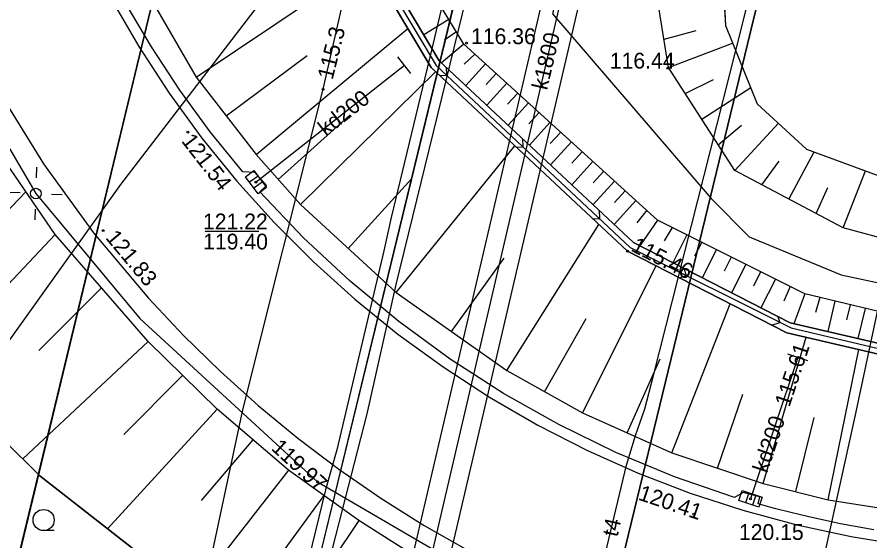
# Model space of a CAD drawing. Extents: x 6424617 to 6425697, y 5665845 to 5667190.
# Drawn here: x 6425461.6 to 6425502.01, y 5666814.14 to 5666838.98 of the extents above; entities that cross this region are included whole.
import ezdxf

# ---------------------------------------------------------------- set-up
doc = ezdxf.new("R2010")
doc.units = 0
for name, color, linetype in [('Warstwa 1', 7, 'Continuous'), ('Warstwa 12', 7, 'Continuous'), ('Warstwa 13', 7, 'Continuous'), ('Warstwa 14', 7, 'Continuous'), ('Warstwa 15', 7, 'Continuous'), ('Warstwa 2', 7, 'Continuous'), ('Warstwa 20', 7, 'Continuous'), ('Warstwa 21', 7, 'Continuous'), ('Warstwa 25', 7, 'Continuous'), ('Warstwa 4', 7, 'Continuous'), ('Warstwa 6', 7, 'Continuous'), ('Warstwa 61', 7, 'Continuous'), ('Warstwa 8', 7, 'Continuous'), ('Warstwa 9', 7, 'Continuous')]:
    doc.layers.add(name, color=color, linetype=linetype)

msp = doc.modelspace()

# ---------------------------------------------------------------- linework, layer by layer
at = {"layer": 'Warstwa 1'}
for p, q in [((6425474.6, 5666748.65), (6425522.252, 5666945.035)), ((6425474.6, 5666748.65), (6425522.252, 5666945.035)), ((6425454.155, 5666782.149), (6425471.236, 5666853.116)), ((6425454.155, 5666782.149), (6425471.236, 5666853.116))]:
    msp.add_line(p, q, dxfattribs=at)
at = {"layer": 'Warstwa 12'}
for points in [[(6425454.75, 5666812.915), (6425455.753, 5666816.883), (6425457.009, 5666817.738), (6425466.513, 5666831.046), (6425477.951, 5666845.959), (6425477.163, 5666847.339), (6425475.812, 5666851.526), (6425475.173, 5666855.074), (6425474.407, 5666861.19), (6425474.538, 5666868.989), (6425475.24, 5666876.27), (6425477.752, 5666888.602), (6425479.441, 5666893.041), (6425480.828, 5666893.587), (6425484.849, 5666908.144), (6425470.76, 5666912.634), (6425469.827, 5666913.063), (6425472.078, 5666923.598), (6425472.03, 5666923.61), (6425482.03, 5666965.191), (6425489.31, 5666994.281), (6425496.49, 5667021.647)], [(6425470.675, 5666812.723), (6425472.304, 5666820.347), (6425476.107, 5666835.553), (6425479.576, 5666850.831), (6425493.276, 5666901.432), (6425493.535, 5666902.072), (6425493.16, 5666902.53), (6425486.027, 5666904.729), (6425481.07, 5666906.403), (6425469.466, 5666909.139), (6425469.101, 5666909.586), (6425469.483, 5666910.214), (6425471.98, 5666923.618), (6425472.03, 5666923.61), (6425482.03, 5666965.191), (6425489.31, 5666994.281), (6425496.49, 5667021.647)], [(6425499.608, 5666812.372), (6425501.312, 5666820.03), (6425502.717, 5666826.643), (6425504.653, 5666835.914), (6425506.015, 5666841.883), (6425506.579, 5666844.134), (6425507.337, 5666847.688), (6425511.705, 5666865.996), (6425515.14, 5666880.945), (6425517.137, 5666889.164), (6425519.622, 5666899.265), (6425524.222, 5666918.678), (6425526.588, 5666928.262), (6425527.475, 5666931.839)], [(6425489.22, 5666812.497), (6425490.474, 5666817.727), (6425490.896, 5666819.13), (6425491.336, 5666820.398), (6425491.737, 5666821.916), (6425495.964, 5666838.649), (6425497.689, 5666845.721), (6425498.913, 5666850.556), (6425503.322, 5666868.321), (6425505.296, 5666876.359), (6425505.681, 5666877.85), (6425506.028, 5666879.322), (6425508.389, 5666888.668), (6425512.199, 5666904.697), (6425513.188, 5666908.441), (6425515.663, 5666918.716), (6425518.264, 5666929.68), (6425518.543, 5666931.101)], [(6425497.683, 5666902.344), (6425491.319, 5666877.188), (6425485.367, 5666852.273), (6425479.594, 5666828.428), (6425475.759, 5666812.66)], [(6425480.155, 5666812.607), (6425490.44, 5666856.731)], [(6425492.103, 5666856.276), (6425481.921, 5666812.585)], [(6425454.04, 5666850.53), (6425455.4, 5666845.1), (6425457.01, 5666840.69), (6425459.99, 5666834.85), (6425462.49, 5666830.61), (6425467.42, 5666824.69), (6425475.84, 5666816.94), (6425483.301, 5666812.571)], [(6425472.92, 5666831.15), (6425479.95, 5666836.7)], [(6425498.59, 5666822.84), (6425496.35, 5666816.13)]]:
    msp.add_lwpolyline(points, dxfattribs=at)
at = {"layer": 'Warstwa 14'}
msp.add_line((6425473.055, 5666828.808), (6425470.509, 5666828.808), dxfattribs=at)
for centre in [(6425476.107, 5666835.553), (6425472.92, 5666831.15), (6425498.59, 5666822.84), (6425475.84, 5666816.94), (6425496.35, 5666816.13)]:
    msp.add_circle(centre, 0.045, dxfattribs=at)
at = {"layer": 'Warstwa 2'}
msp.add_lwpolyline([(6425506.88, 5666899.5), (6425503.781, 5666900.196), (6425486.964, 5666839.13), (6425494.478, 5666830.381), (6425496.276, 5666828.558), (6425500.644, 5666826.749), (6425510.918, 5666824.552), (6425520.412, 5666825.171), (6425529.858, 5666828.662), (6425537.889, 5666834.639), (6425544.658, 5666842.259), (6425549.605, 5666852.483), (6425550.773, 5666856.833), (6425551.852, 5666866.697), (6425550.934, 5666876.787), (6425548.326, 5666886.387), (6425542.173, 5666894.101), (6425528.149, 5666899.626), (6425515.187, 5666901.43), (6425512.303, 5666898.502), (6425510.878, 5666898.777)], dxfattribs=at)
msp.add_circle((6425462.49, 5666830.61), 0.25, dxfattribs=at)
at = {"layer": 'Warstwa 20'}
for points in [[(6425553.362, 5666853.356), (6425550.94, 5666852.09), (6425549.89, 5666849.42), (6425546.52, 5666842.87), (6425542.73, 5666837.38), (6425535.81, 5666831.03), (6425527.38, 5666826.39), (6425518.91, 5666823.71), (6425508.93, 5666823.45), (6425498.92, 5666825.85), (6425491.94, 5666829.35), (6425482.77, 5666837.69), (6425477.07, 5666847.09), (6425474.62, 5666856.16), (6425473.75, 5666866.03), (6425474.86, 5666875.89), (6425476.95, 5666886.84), (6425486.39, 5666917.66), (6425485.183, 5666918.688), (6425484.95, 5666918.78)], [(6425527.173, 5666830.091), (6425521.012, 5666827.921), (6425513.022, 5666826.965), (6425506.638, 5666827.381), (6425500.735, 5666828.978), (6425495.602, 5666831.701), (6425492.469, 5666836.579), (6425491.597, 5666841.997), (6425492.669, 5666848.17), (6425494.303, 5666855.052), (6425496.377, 5666864.638), (6425499.03, 5666874.163), (6425501.822, 5666883.666), (6425504.791, 5666895.166), (6425507.053, 5666899.127)], [(6425461.776, 5666863.542), (6425462.587, 5666855.825), (6425463.836, 5666850.201), (6425464.965, 5666846.225), (6425466.204, 5666842.856), (6425470.084, 5666836.133), (6425472.923, 5666832.458), (6425475.027, 5666830.092), (6425479.556, 5666825.924), (6425484.798, 5666822.213), (6425488.384, 5666820.211), (6425492.62, 5666818.321), (6425496.943, 5666816.862), (6425500.032, 5666816.086), (6425505.767, 5666815.182), (6425511.615, 5666814.977), (6425517.376, 5666815.473), (6425523.099, 5666816.62), (6425528.634, 5666818.471)], [(6425481.867, 5666812.588), (6425481.221, 5666812.926), (6425477.791, 5666815.103), (6425474.465, 5666817.491), (6425471.081, 5666820.378), (6425467.805, 5666823.596), (6425463.4, 5666828.674), (6425460.629, 5666832.713), (6425458.029, 5666837.277), (6425455.963, 5666841.717), (6425454.719, 5666845.111), (6425453.384, 5666849.709)]]:
    msp.add_lwpolyline(points, dxfattribs=at)
at = {"layer": 'Warstwa 21'}
for p, q in [((6425480.26, 5666836.308), (6425479.64, 5666837.092)), ((6425499.065, 5666822.683), (6425498.115, 5666822.997))]:
    msp.add_line(p, q, dxfattribs=at)
for points in [[(6425484.95, 5666918.78), (6425484.833, 5666917.264), (6425485.3, 5666917.095), (6425478.237, 5666897.116), (6425475.766, 5666887.097), (6425473.486, 5666876.065), (6425472.598, 5666865.688), (6425473.371, 5666855.87), (6425475.777, 5666846.714), (6425481.602, 5666836.906), (6425490.809, 5666828.287), (6425498.233, 5666824.471), (6425508.632, 5666822.063), (6425519.743, 5666822.432), (6425527.817, 5666824.757), (6425536.828, 5666829.656), (6425543.832, 5666835.802), (6425548.243, 5666841.884), (6425551.55, 5666848.658), (6425553.362, 5666853.356)], [(6425528.009, 5666824.294), (6425519.824, 5666821.941), (6425508.583, 5666821.554), (6425498.064, 5666824.004), (6425490.521, 5666827.872), (6425481.216, 5666836.593), (6425475.303, 5666846.513), (6425472.88, 5666855.789), (6425472.098, 5666865.687), (6425472.997, 5666876.134), (6425475.278, 5666887.206), (6425477.76, 5666897.255), (6425484.833, 5666917.264)], [(6425507.053, 5666899.127), (6425505.53, 5666891.812), (6425504.069, 5666884.586), (6425503.174, 5666880.42), (6425501.832, 5666873.682), (6425500.85, 5666868.589), (6425500.275, 5666865.548), (6425499.288, 5666861.334), (6425498.064, 5666856.115), (6425496.122, 5666847.767), (6425494.952, 5666842.767), (6425495.156, 5666838.572), (6425496.67, 5666834.863), (6425499.002, 5666832.72), (6425505.401, 5666830.354), (6425509.993, 5666829.821), (6425515.794, 5666829.796), (6425520.41, 5666830.593), (6425526.02, 5666832.712)], [(6425468.392, 5666812.751), (6425462.681, 5666817.231), (6425457.481, 5666822.356), (6425456.019, 5666822.263), (6425453.384, 5666849.709)]]:
    msp.add_lwpolyline(points, dxfattribs=at)
at = {"layer": 'Warstwa 25'}
for centre in [(6425482.891, 5666837.735), (6425492.435, 5666836.548), (6425469.695, 5666833.516), (6425465.676, 5666828.85), (6425490.521, 5666827.872), (6425493.663, 5666815.401)]:
    msp.add_circle(centre, 0.045, dxfattribs=at)
at = {"layer": 'Warstwa 4'}
for p, q in [((6425473.017, 5666831.439), (6425472.615, 5666831.142)), ((6425473.225, 5666831.158), (6425472.823, 5666830.861)), ((6425496.266, 5666816.423), (6425496.103, 5666815.95)), ((6425496.597, 5666816.31), (6425496.434, 5666815.837))]:
    msp.add_line(p, q, dxfattribs=at)
for points in [[(6425462.52, 5666831.359), (6425462.539, 5666831.859)], [(6425461.741, 5666830.64), (6425461.241, 5666830.659)], [(6425463.239, 5666830.58), (6425463.739, 5666830.561)], [(6425462.46, 5666829.861), (6425462.441, 5666829.361)]]:
    msp.add_lwpolyline(points, dxfattribs=at)
for points in [[(6425472.824, 5666831.701), (6425473.418, 5666830.897), (6425473.016, 5666830.599), (6425472.422, 5666831.403)], [(6425495.958, 5666816.529), (6425496.904, 5666816.204), (6425496.742, 5666815.731), (6425495.796, 5666816.056)]]:
    msp.add_lwpolyline(points, close=True, dxfattribs=at)
at = {"layer": 'Warstwa 6'}
msp.add_line((6425463.36, 5666814.627), (6425462.86, 5666814.627), dxfattribs=at)
for points in [[(6425493.084, 5667022.41), (6425437.407, 5666792.342), (6425454.155, 5666782.149), (6425471.236, 5666853.116), (6425495.139, 5666950.762), (6425496.12, 5666954.85), (6425485.36, 5666958.9), (6425501.348, 5667020.558)], [(6425474.6, 5666748.65), (6425522.252, 5666945.035), (6425496.12, 5666954.85), (6425495.139, 5666950.762), (6425471.236, 5666853.116), (6425454.155, 5666782.149)], [(6425569.514, 5666914.463), (6425559.46, 5666924.76), (6425550.86, 5666931.17), (6425537.49, 5666938.32), (6425528.13, 5666942.39), (6425522.252, 5666945.035), (6425474.6, 5666748.65), (6425499.79, 5666763.64), (6425538.28, 5666785.28), (6425540.993, 5666787.253)], [(6425502.194, 5666814.659), (6425501.402, 5666814.798), (6425500.613, 5666814.95), (6425499.826, 5666815.115), (6425499.042, 5666815.292), (6425498.26, 5666815.481), (6425497.482, 5666815.682), (6425496.707, 5666815.896), (6425496.783, 5666816.235), (6425496.007, 5666816.439), (6425495.592, 5666816.196), (6425492.75, 5666817.183), (6425489.972, 5666818.337), (6425487.267, 5666819.654), (6425484.646, 5666821.131), (6425482.118, 5666822.762), (6425479.692, 5666824.54), (6425477.376, 5666826.46), (6425475.178, 5666828.515), (6425473.107, 5666830.697), (6425473.422, 5666830.991), (6425472.883, 5666831.601), (6425472.294, 5666831.632), (6425470.756, 5666833.537), (6425469.313, 5666835.515), (6425467.968, 5666837.562), (6425466.726, 5666839.672)]]:
    msp.add_lwpolyline(points, dxfattribs=at)
msp.add_circle((6425462.86, 5666815.127), 0.5, dxfattribs=at)
at = {"layer": 'Warstwa 61'}
for points in [[(6425481.038, 5666812.596), (6425491.4, 5666857.132), (6425513.738, 5666949.133), (6425526.476, 5667002.476), (6425529.291, 5667014.292)], [(6425475.766, 5666812.66), (6425481.972, 5666838.27), (6425489.663, 5666870.793), (6425494.666, 5666890.633), (6425505.914, 5666939.966)]]:
    msp.add_lwpolyline(points, dxfattribs=at)
at = {"layer": 'Warstwa 8'}
for p, q in [((6425494.952, 5666842.767), (6425495.156, 5666838.572)), ((6425466.05, 5666839.867), (6425467.368, 5666837.584)), ((6425495.156, 5666838.572), (6425496.67, 5666834.863)), ((6425467.368, 5666837.584), (6425468.804, 5666835.372)), ((6425460.727, 5666835.449), (6425462.86, 5666832.019)), ((6425468.804, 5666835.372), (6425470.353, 5666833.239)), ((6425496.67, 5666834.863), (6425499.002, 5666832.72)), ((6425470.353, 5666833.239), (6425472.012, 5666831.189)), ((6425499.002, 5666832.72), (6425505.401, 5666830.354)), ((6425462.86, 5666832.019), (6425465.23, 5666828.748)), ((6425472.012, 5666831.189), (6425473.776, 5666829.229)), ((6425473.776, 5666829.229), (6425475.64, 5666827.364)), ((6425465.23, 5666828.748), (6425467.824, 5666825.651)), ((6425475.64, 5666827.364), (6425477.599, 5666825.599)), ((6425467.824, 5666825.651), (6425469.486, 5666823.88)), ((6425477.599, 5666825.599), (6425479.647, 5666823.939)), ((6425469.486, 5666823.88), (6425471.222, 5666822.181)), ((6425479.647, 5666823.939), (6425481.78, 5666822.388)), ((6425471.222, 5666822.181), (6425473.029, 5666820.557)), ((6425481.78, 5666822.388), (6425483.99, 5666820.95)), ((6425483.99, 5666820.95), (6425486.271, 5666819.63)), ((6425473.029, 5666820.557), (6425474.902, 5666819.011)), ((6425486.271, 5666819.63), (6425488.618, 5666818.43)), ((6425474.902, 5666819.011), (6425476.84, 5666817.547)), ((6425488.618, 5666818.43), (6425491.025, 5666817.355)), ((6425476.84, 5666817.547), (6425478.838, 5666816.166)), ((6425491.025, 5666817.355), (6425493.484, 5666816.407)), ((6425478.838, 5666816.166), (6425480.893, 5666814.871)), ((6425493.484, 5666816.407), (6425495.99, 5666815.588)), ((6425495.99, 5666815.588), (6425498.535, 5666814.901)), ((6425480.893, 5666814.871), (6425483.001, 5666813.664)), ((6425498.535, 5666814.901), (6425501.112, 5666814.347)), ((6425501.112, 5666814.347), (6425503.714, 5666813.929))]:
    msp.add_line(p, q, dxfattribs=at)
for points in [[(6425498.906, 5666909.713), (6425496.931, 5666900.782), (6425494.212, 5666890.683), (6425492.101, 5666882.567), (6425490.044, 5666874.756), (6425487.099, 5666862.108), (6425484.446, 5666850.937), (6425481.232, 5666837.406), (6425479.319, 5666829.467), (6425478.976, 5666827.889), (6425476.745, 5666818.46), (6425476.217, 5666816.552), (6425475.27, 5666812.666)], [(6425476.261, 5666812.654), (6425478.183, 5666820.161), (6425479.563, 5666826.303), (6425482.711, 5666839.133), (6425484.905, 5666848.69), (6425486.73, 5666856.146), (6425489.281, 5666866.829), (6425492.386, 5666879.369), (6425494.39, 5666887.252), (6425495.12, 5666890.582), (6425497.769, 5666901.057), (6425499.005, 5666906.199)], [(6425457.009, 5666817.738), (6425466.513, 5666831.046), (6425477.951, 5666845.959)]]:
    msp.add_lwpolyline(points, dxfattribs=at)
at = {"layer": 'Warstwa 9'}
for p, q in [((6425475.56, 5666846.602), (6425481.45, 5666836.677)), ((6425470.084, 5666836.133), (6425478.233, 5666841.598)), ((6425482.057, 5666838.865), (6425480.867, 5666838.143)), ((6425472.923, 5666832.458), (6425480.12, 5666838.431)), ((6425482.414, 5666838.278), (6425481.849, 5666837.877)), ((6425492.251, 5666837.933), (6425493.774, 5666838.346)), ((6425482.77, 5666837.69), (6425481.703, 5666836.812)), ((6425492.469, 5666836.579), (6425495.497, 5666837.737)), ((6425471.504, 5666834.296), (6425475.34, 5666837.155)), ((6425483.28, 5666837.226), (6425482.779, 5666836.75)), ((6425481.45, 5666836.677), (6425490.649, 5666828.057)), ((6425483.789, 5666836.763), (6425482.854, 5666835.735)), ((6425475.027, 5666830.092), (6425481.433, 5666836.39)), ((6425481.928, 5666836.601), (6425481.941, 5666836.217)), ((6425484.298, 5666836.3), (6425483.828, 5666835.782)), ((6425481.628, 5666836.207), (6425481.941, 5666836.217)), ((6425493.252, 5666835.36), (6425494.59, 5666836.022)), ((6425484.808, 5666835.837), (6425483.859, 5666834.793)), ((6425494.036, 5666834.14), (6425496.357, 5666835.631)), ((6425485.318, 5666835.374), (6425484.84, 5666834.848)), ((6425485.827, 5666834.91), (6425484.865, 5666833.852)), ((6425473.975, 5666831.275), (6425477.376, 5666834.343)), ((6425486.336, 5666834.446), (6425485.852, 5666833.914)), ((6425486.846, 5666833.983), (6425485.871, 5666832.91)), ((6425494.819, 5666832.92), (6425495.916, 5666833.854)), ((6425495.602, 5666831.701), (6425497.667, 5666833.946)), ((6425487.355, 5666833.52), (6425486.864, 5666832.98)), ((6425485.552, 5666833.208), (6425485.565, 5666832.821)), ((6425487.864, 5666833.057), (6425486.875, 5666831.97)), ((6425479.556, 5666825.924), (6425485.18, 5666832.878)), ((6425485.251, 5666832.811), (6425485.565, 5666832.821)), ((6425488.374, 5666832.593), (6425487.876, 5666832.046)), ((6425498.169, 5666830.34), (6425499.361, 5666832.587)), ((6425488.883, 5666832.13), (6425487.881, 5666831.028)), ((6425496.886, 5666831.021), (6425497.7, 5666832.144)), ((6425489.392, 5666831.666), (6425488.888, 5666831.112)), ((6425500.735, 5666828.978), (6425501.802, 5666831.685)), ((6425477.292, 5666828.008), (6425480.299, 5666831.321)), ((6425489.902, 5666831.203), (6425488.887, 5666830.086)), ((6425462.014, 5666830.694), (6425459.046, 5666827.605)), ((6425490.411, 5666830.74), (6425489.9, 5666830.178)), ((6425499.452, 5666829.659), (6425500.017, 5666830.898)), ((6425490.921, 5666830.277), (6425489.892, 5666829.145)), ((6425489.176, 5666829.816), (6425489.188, 5666829.426)), ((6425491.43, 5666829.814), (6425490.965, 5666829.226)), ((6425488.874, 5666829.415), (6425489.188, 5666829.426)), ((6425484.798, 5666822.213), (6425489.166, 5666829.142)), ((6425491.94, 5666829.35), (6425491.106, 5666828.134)), ((6425492.638, 5666829), (6425492.264, 5666828.365)), ((6425463.4, 5666828.674), (6425457.481, 5666822.356)), ((6425493.336, 5666828.65), (6425492.674, 5666827.328)), ((6425494.034, 5666828.3), (6425493.701, 5666827.636)), ((6425490.649, 5666828.057), (6425498.267, 5666824.234)), ((6425494.732, 5666827.95), (6425494.063, 5666826.614)), ((6425482.177, 5666824.068), (6425484.675, 5666827.539)), ((6425495.43, 5666827.6), (6425495.094, 5666826.928)), ((6425488.384, 5666820.211), (6425491.872, 5666827.179)), ((6425493.187, 5666827.065), (6425493.299, 5666826.727)), ((6425496.128, 5666827.25), (6425495.452, 5666825.9)), ((6425492.968, 5666826.617), (6425493.299, 5666826.727)), ((6425496.826, 5666826.9), (6425496.486, 5666826.222)), ((6425497.524, 5666826.55), (6425496.841, 5666825.187)), ((6425498.222, 5666826.2), (6425497.922, 5666825.505)), ((6425465.602, 5666826.135), (6425462.64, 5666823.163)), ((6425498.92, 5666825.85), (6425498.403, 5666824.432)), ((6425492.62, 5666818.321), (6425495.378, 5666825.382)), ((6425499.635, 5666825.678), (6425499.419, 5666824.962)), ((6425500.35, 5666825.507), (6425500.004, 5666824.061)), ((6425501.065, 5666825.336), (6425500.892, 5666824.616)), ((6425501.78, 5666825.164), (6425501.436, 5666823.73)), ((6425486.591, 5666821.212), (6425488.555, 5666824.686)), ((6425497.647, 5666824.772), (6425497.738, 5666824.499)), ((6425497.349, 5666824.371), (6425497.738, 5666824.499)), ((6425498.267, 5666824.234), (6425508.7, 5666821.786)), ((6425496.943, 5666816.862), (6425498.978, 5666823.791)), ((6425467.805, 5666823.596), (6425461.876, 5666818.025)), ((6425500.032, 5666816.086), (6425501.484, 5666823.207)), ((6425490.502, 5666819.266), (6425492.064, 5666822.773)), ((6425469.443, 5666821.987), (6425466.663, 5666819.178)), ((6425494.782, 5666817.592), (6425495.98, 5666821.089)), ((6425471.081, 5666820.378), (6425465.891, 5666814.712)), ((6425498.488, 5666816.474), (6425499.359, 5666819.986)), ((6425472.773, 5666818.934), (6425470.325, 5666816.049)), ((6425474.465, 5666817.491), (6425470.731, 5666812.723)), ((6425476.128, 5666816.297), (6425473.942, 5666813.294)), ((6425477.791, 5666815.103), (6425476.139, 5666812.657))]:
    msp.add_line(p, q, dxfattribs=at)
for points in [[(6425527.38, 5666826.39), (6425518.91, 5666823.71), (6425508.93, 5666823.45), (6425498.92, 5666825.85), (6425491.94, 5666829.35), (6425482.77, 5666837.69), (6425477.07, 5666847.09), (6425474.62, 5666856.16), (6425473.75, 5666866.03), (6425474.86, 5666875.89), (6425476.95, 5666886.84), (6425486.39, 5666917.66)], [(6425484.833, 5666917.264), (6425477.76, 5666897.255), (6425475.278, 5666887.206), (6425472.997, 5666876.134), (6425472.098, 5666865.687), (6425472.88, 5666855.789), (6425475.303, 5666846.513), (6425481.216, 5666836.593), (6425490.521, 5666827.872), (6425498.064, 5666824.004), (6425508.583, 5666821.554), (6425519.824, 5666821.941), (6425528.009, 5666824.294)], [(6425528.009, 5666824.294), (6425519.824, 5666821.941), (6425508.583, 5666821.554), (6425498.064, 5666824.004), (6425490.521, 5666827.872), (6425481.216, 5666836.593), (6425475.303, 5666846.513), (6425472.88, 5666855.789), (6425472.098, 5666865.687), (6425472.997, 5666876.134), (6425475.278, 5666887.206), (6425477.76, 5666897.255), (6425484.833, 5666917.264)], [(6425527.817, 5666824.757), (6425519.743, 5666822.432), (6425508.632, 5666822.063), (6425498.233, 5666824.471), (6425490.809, 5666828.287), (6425481.602, 5666836.906), (6425475.777, 5666846.714), (6425473.371, 5666855.87), (6425472.598, 5666865.688), (6425473.486, 5666876.065), (6425475.766, 5666887.097), (6425478.237, 5666897.116), (6425485.3, 5666917.095)], [(6425485.3, 5666917.095), (6425478.237, 5666897.116), (6425475.766, 5666887.097), (6425473.486, 5666876.065), (6425472.598, 5666865.688), (6425473.371, 5666855.87), (6425475.777, 5666846.714), (6425481.602, 5666836.906), (6425490.809, 5666828.287), (6425498.233, 5666824.471), (6425508.632, 5666822.063), (6425519.743, 5666822.432), (6425527.817, 5666824.757)], [(6425527.173, 5666830.091), (6425521.012, 5666827.921), (6425513.022, 5666826.965), (6425506.638, 5666827.381), (6425500.735, 5666828.978), (6425495.602, 5666831.701), (6425492.469, 5666836.579), (6425491.597, 5666841.997), (6425492.669, 5666848.17), (6425494.303, 5666855.052), (6425496.377, 5666864.638)], [(6425461.776, 5666863.542), (6425462.587, 5666855.825), (6425463.836, 5666850.201), (6425464.965, 5666846.225), (6425466.204, 5666842.856), (6425470.084, 5666836.133), (6425472.923, 5666832.458), (6425475.027, 5666830.092), (6425479.556, 5666825.924), (6425484.798, 5666822.213), (6425488.384, 5666820.211), (6425492.62, 5666818.321), (6425496.943, 5666816.862), (6425500.032, 5666816.086), (6425505.767, 5666815.182), (6425511.615, 5666814.977), (6425517.376, 5666815.473), (6425523.099, 5666816.62), (6425528.634, 5666818.471)], [(6425499.288, 5666861.334), (6425498.064, 5666856.115), (6425496.122, 5666847.767), (6425494.952, 5666842.767), (6425495.156, 5666838.572), (6425496.67, 5666834.863), (6425499.002, 5666832.72), (6425505.401, 5666830.354), (6425509.993, 5666829.821), (6425515.794, 5666829.796), (6425520.41, 5666830.593), (6425526.02, 5666832.712)]]:
    msp.add_lwpolyline(points, dxfattribs=at)
msp.add_lwpolyline([(6425481.867, 5666812.588), (6425481.221, 5666812.926), (6425477.791, 5666815.103), (6425474.465, 5666817.491), (6425471.081, 5666820.378), (6425467.805, 5666823.596), (6425463.4, 5666828.674), (6425460.629, 5666832.713), (6425458.029, 5666837.277), (6425455.963, 5666841.717), (6425454.719, 5666845.111), (6425453.384, 5666849.709), (6425456.019, 5666822.263), (6425457.481, 5666822.356), (6425462.681, 5666817.231), (6425468.392, 5666812.751)], close=True, dxfattribs=at)

# ---------------------------------------------------------------- texts
at = {"layer": 'Warstwa 13'}
for s, rotation, p in [('k1800', 76.8795, (6425486.709, 5666835.481)), ('kd200', 38.2908, (6425476.233, 5666833.298)), ('kd200', 71.5395, (6425497.136, 5666817.32)), ('t4', 77.2175, (6425490.042, 5666814.295))]:
    msp.add_text(s, height=0.75, rotation=rotation, dxfattribs=at).set_placement(p)
at = {"layer": 'Warstwa 14'}
for s, rotation, p in [('115.3', 75.957, (6425476.547, 5666835.972)), ('115.61', 71.5395, (6425498.188, 5666820.45)), ('119.97', 317.3728, (6425473.601, 5666818.491))]:
    msp.add_text(s, height=0.75, rotation=rotation, dxfattribs=at).set_placement(p)
msp.add_text('119.40', height=0.75, dxfattribs=at).set_placement((6425470.417, 5666827.956))
at = {"layer": 'Warstwa 15'}
for s, p in [('121.22', (6425470.408, 5666828.911)), ('120.15', (6425495.8, 5666814.185))]:
    msp.add_text(s, height=0.75, dxfattribs=at).set_placement(p)
at = {"layer": 'Warstwa 25'}
for s, p in [('116.36', (6425483.108, 5666837.693)), ('116.44', (6425489.682, 5666836.536))]:
    msp.add_text(s, height=0.75, dxfattribs=at).set_placement(p)
for s, rotation, p in [('121.54', 307.6841, (6425469.356, 5666833.096)), ('121.83', 309.7868, (6425465.758, 5666828.501)), ('115.46', 332.8541, (6425490.641, 5666827.914)), ('120.41', 341.3511, (6425490.988, 5666816.102))]:
    msp.add_text(s, height=0.75, rotation=rotation, dxfattribs=at).set_placement(p)

doc.saveas('drawing.dxf')
